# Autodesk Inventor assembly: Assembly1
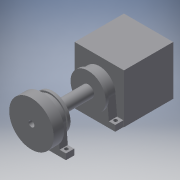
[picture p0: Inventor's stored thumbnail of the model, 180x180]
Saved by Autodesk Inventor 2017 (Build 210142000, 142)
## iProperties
Created: 2017-04
Part Number: Assembly1
Document SubType Name: Assembly
Designer: s4321966
Author: s4321966
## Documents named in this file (6)
- \\puffball.labs.eait.uq.edu.au\s4321966\Documents\metr4810_spool draft\Assembly1.iam
- \\puffball.labs.eait.uq.edu.au\s4321966\Documents\metr4810_spool draft\nema17.ipt
- \\puffball.labs.eait.uq.edu.au\s4321966\Documents\metr4810_spool draft\spool.ipt
- \\puffball.labs.eait.uq.edu.au\s4321966\Documents\metr4810_spool draft\std_bearing.ipt
- \\puffball.labs.eait.uq.edu.au\s4321966\Documents\metr4810_spool draft\mount.ipt
- \\puffball.labs.eait.uq.edu.au\s4321966\Documents\metr4810_spool draft\slipring.ipt
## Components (7 placed, 5 different names)
1. nema17:1 — Rotational:1, Flush:3, Flush:4
2. spool:1 — Cylindrical:1, Flush:1, Cylindrical:2, Flush:2, Mate:1, Mate:2, Cylindrical:5
3. std_bearing:1 — Cylindrical:1, Flush:1, Cylindrical:3
4. std_bearing:2 — Cylindrical:2, Flush:2, Rotational:1, Cylindrical:4
5. mount:1 — Flush:4, Cylindrical:3, Mate:1, Mate:3
6. mount:2 — Flush:3, Cylindrical:4, Mate:2
7. slipring:1 — Mate:3, Cylindrical:5
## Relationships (13: CylindricalJoint 5, Flush 4, Mate 3, RevoluteJoint 1)
- Cylindrical:1: spool:1 ↔ std_bearing:1
- Flush:1: spool:1 ↔ std_bearing:1
- Cylindrical:2: spool:1 ↔ std_bearing:2
- Flush:2: spool:1 ↔ std_bearing:2
- Rotational:1 [RevoluteJoint]: nema17:1 ↔ std_bearing:2
- Flush:3: nema17:1 ↔ mount:2
- Flush:4: nema17:1 ↔ mount:1
- Cylindrical:3: std_bearing:1 ↔ mount:1
- Cylindrical:4: std_bearing:2 ↔ mount:2
- Mate:1: spool:1 ↔ mount:1
- Mate:2: spool:1 ↔ mount:2
- Mate:3: mount:1 ↔ slipring:1
- Cylindrical:5: spool:1 ↔ slipring:1
